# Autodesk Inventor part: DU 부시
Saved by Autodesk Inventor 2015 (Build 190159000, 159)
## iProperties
Created: 2025-11
Part Number: DU 부시
Material: 일반
Document SubType Name: Modeling
Designer: user
Density: 1 g/cm^3
Appearance: 기본값
Author: user
Author: jhkim
Creation Date: 2025-10-31
Sending System: Autodesk Inventor 2026
Preprocessor: ST-DEVELOPER v20.1
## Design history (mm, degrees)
node "DU 부시1"
node "솔리드1"
node "기준1"
